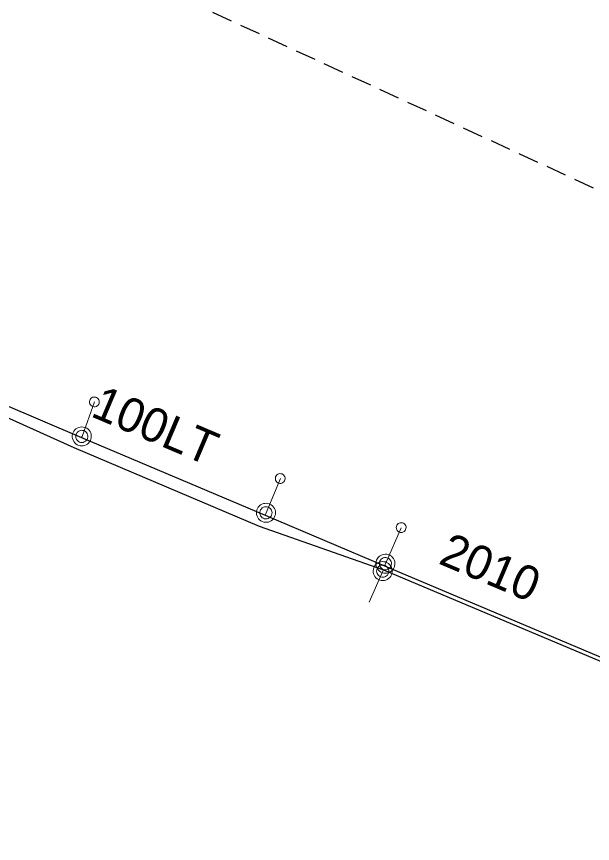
# Model space of a CAD drawing. Extents: x -735085 to -733500, y -1044153 to -1043402.
# Drawn here: x -734785.04 to -734758, y -1043558.45 to -1043519.6 of the extents above; entities that cross this region are included whole.
import ezdxf

# ---------------------------------------------------------------- set-up
doc = ezdxf.new("R2010")
doc.units = 0
doc.header["$LTSCALE"] = 0.32
doc.linetypes.add('MEDIUM_DASHED', pattern=[4.5, 3, -1.5])
doc.layers.add('15', color=7, linetype='Continuous')
doc.layers.add('63', color=7, linetype='MEDIUM_DASHED', lineweight=25)
doc.layers.add('8', color=7, linetype='Continuous', lineweight=13)

msp = doc.modelspace()

# ---------------------------------------------------------------- linework, layer by layer
at = {"layer": '63'}
msp.add_lwpolyline([(-734796.022, -1043808.279), (-734957.658, -1043641.023), (-734957.66, -1043641.021), (-735032.487, -1043496.398), (-735032.488, -1043496.396), (-735032.488, -1043496.394), (-735032.488, -1043496.393), (-735032.488, -1043496.391), (-735014.686, -1043433.916), (-735014.686, -1043433.914), (-735014.685, -1043433.913), (-735014.683, -1043433.911), (-735014.682, -1043433.91), (-735014.68, -1043433.909), (-735014.678, -1043433.909), (-735014.676, -1043433.909), (-734957.569, -1043435.5), (-734957.567, -1043435.5), (-734957.565, -1043435.501), (-734250.468, -1043761.931)], dxfattribs=at)
at = {"layer": '8'}
for p, q in [((-734767.84, -1043545.66), (-734768.48, -1043547.117)), ((-734767.807, -1043545.587), (-734767.84, -1043545.66))]:
    msp.add_line(p, q, dxfattribs=at)
at = {"layer": '8', "lineweight": 25}
for points in [[(-734798.6, -1043532.29), (-734781.989, -1043539.38), (-734773.37, -1043543.03), (-734767.76, -1043545.41), (-734738.719, -1043557.66), (-734737.059, -1043558.35)], [(-734792.71, -1043535.18), (-734782.352, -1043539.852), (-734773.644, -1043543.536), (-734767.807, -1043545.587), (-734738.734, -1043557.836), (-734732.528, -1043560.258), (-734709.46, -1043569.477), (-734674.151, -1043584.087)]]:
    msp.add_lwpolyline(points, dxfattribs=at)
at = {"layer": '8'}
for points in [[(-734781.315, -1043537.487), (-734781.366, -1043537.476), (-734781.419, -1043537.477), (-734781.47, -1043537.49), (-734781.517, -1043537.514), (-734781.557, -1043537.548), (-734781.588, -1043537.59), (-734781.609, -1043537.638), (-734781.619, -1043537.689), (-734781.617, -1043537.742), (-734781.603, -1043537.793), (-734781.577, -1043537.839), (-734781.542, -1043537.878), (-734781.499, -1043537.908), (-734781.451, -1043537.928), (-734781.399, -1043537.937), (-734781.347, -1043537.932), (-734781.296, -1043537.918), (-734781.25, -1043537.891), (-734781.213, -1043537.855), (-734781.183, -1043537.811), (-734781.165, -1043537.763), (-734781.158, -1043537.71), (-734781.163, -1043537.658), (-734781.18, -1043537.608), (-734781.207, -1043537.564), (-734781.244, -1043537.526), (-734781.289, -1043537.498)], [(-734781.835, -1043538.903), (-734781.907, -1043538.885), (-734781.98, -1043538.879), (-734782.052, -1043538.885), (-734782.123, -1043538.904), (-734782.191, -1043538.933), (-734782.252, -1043538.972), (-734782.305, -1043539.022), (-734782.351, -1043539.079), (-734782.386, -1043539.143), (-734782.411, -1043539.213), (-734782.424, -1043539.285), (-734782.424, -1043539.358), (-734782.413, -1043539.429), (-734782.391, -1043539.499), (-734782.357, -1043539.565), (-734782.313, -1043539.623), (-734782.259, -1043539.674), (-734782.199, -1043539.715), (-734782.133, -1043539.746), (-734782.062, -1043539.765), (-734781.99, -1043539.773), (-734781.917, -1043539.769), (-734781.845, -1043539.753), (-734781.778, -1043539.725), (-734781.715, -1043539.687), (-734781.66, -1043539.639), (-734781.613, -1043539.584), (-734781.575, -1043539.52), (-734781.549, -1043539.452), (-734781.534, -1043539.38), (-734781.532, -1043539.307), (-734781.541, -1043539.234), (-734781.562, -1043539.164), (-734781.593, -1043539.098), (-734781.636, -1043539.038), (-734781.687, -1043538.986), (-734781.747, -1043538.944), (-734781.812, -1043538.912)], [(-734781.887, -1043539.055), (-734781.944, -1043539.042), (-734782.003, -1043539.041), (-734782.06, -1043539.052), (-734782.114, -1043539.075), (-734782.163, -1043539.107), (-734782.204, -1043539.149), (-734782.235, -1043539.198), (-734782.256, -1043539.254), (-734782.265, -1043539.311), (-734782.261, -1043539.37), (-734782.247, -1043539.427), (-734782.221, -1043539.479), (-734782.185, -1043539.525), (-734782.14, -1043539.563), (-734782.089, -1043539.591), (-734782.032, -1043539.608), (-734781.974, -1043539.613), (-734781.916, -1043539.606), (-734781.861, -1043539.587), (-734781.81, -1043539.557), (-734781.767, -1043539.518), (-734781.732, -1043539.471), (-734781.707, -1043539.418), (-734781.695, -1043539.361), (-734781.693, -1043539.302), (-734781.704, -1043539.245), (-734781.727, -1043539.19), (-734781.759, -1043539.143), (-734781.801, -1043539.102), (-734781.851, -1043539.07)], [(-734772.573, -1043541.091), (-734772.624, -1043541.077), (-734772.677, -1043541.076), (-734772.728, -1043541.085), (-734772.777, -1043541.107), (-734772.818, -1043541.139), (-734772.851, -1043541.18), (-734772.875, -1043541.226), (-734772.888, -1043541.277), (-734772.888, -1043541.33), (-734772.877, -1043541.382), (-734772.853, -1043541.429), (-734772.821, -1043541.469), (-734772.779, -1043541.502), (-734772.732, -1043541.524), (-734772.68, -1043541.536), (-734772.628, -1043541.534), (-734772.577, -1043541.522), (-734772.53, -1043541.497), (-734772.491, -1043541.463), (-734772.459, -1043541.421), (-734772.438, -1043541.374), (-734772.428, -1043541.321), (-734772.431, -1043541.269), (-734772.445, -1043541.218), (-734772.47, -1043541.173), (-734772.505, -1043541.133), (-734772.548, -1043541.103)], [(-734773.165, -1043542.5), (-734773.235, -1043542.479), (-734773.308, -1043542.469), (-734773.381, -1043542.472), (-734773.452, -1043542.486), (-734773.521, -1043542.512), (-734773.584, -1043542.548), (-734773.64, -1043542.595), (-734773.689, -1043542.65), (-734773.727, -1043542.712), (-734773.755, -1043542.78), (-734773.772, -1043542.851), (-734773.776, -1043542.925), (-734773.769, -1043542.997), (-734773.75, -1043543.068), (-734773.719, -1043543.135), (-734773.678, -1043543.195), (-734773.628, -1043543.248), (-734773.57, -1043543.293), (-734773.505, -1043543.327), (-734773.436, -1043543.35), (-734773.364, -1043543.361), (-734773.29, -1043543.361), (-734773.218, -1043543.349), (-734773.149, -1043543.325), (-734773.085, -1043543.29), (-734773.027, -1043543.245), (-734772.977, -1043543.192), (-734772.937, -1043543.13), (-734772.907, -1043543.063), (-734772.889, -1043542.992), (-734772.882, -1043542.919), (-734772.888, -1043542.846), (-734772.905, -1043542.775), (-734772.933, -1043542.708), (-734772.973, -1043542.646), (-734773.021, -1043542.591), (-734773.079, -1043542.546), (-734773.142, -1043542.51)], [(-734773.224, -1043542.65), (-734773.28, -1043542.634), (-734773.339, -1043542.63), (-734773.397, -1043542.637), (-734773.452, -1043542.657), (-734773.502, -1043542.687), (-734773.545, -1043542.727), (-734773.579, -1043542.775), (-734773.603, -1043542.829), (-734773.614, -1043542.886), (-734773.614, -1043542.945), (-734773.602, -1043543.002), (-734773.579, -1043543.055), (-734773.545, -1043543.103), (-734773.502, -1043543.144), (-734773.453, -1043543.174), (-734773.397, -1043543.194), (-734773.339, -1043543.202), (-734773.281, -1043543.198), (-734773.225, -1043543.182), (-734773.172, -1043543.155), (-734773.128, -1043543.118), (-734773.09, -1043543.073), (-734773.063, -1043543.021), (-734773.048, -1043542.965), (-734773.043, -1043542.906), (-734773.051, -1043542.848), (-734773.071, -1043542.793), (-734773.101, -1043542.744), (-734773.141, -1043542.701), (-734773.189, -1043542.667)], [(-734766.753, -1043543.572), (-734766.767, -1043543.522), (-734766.793, -1043543.476), (-734766.828, -1043543.437), (-734766.871, -1043543.406), (-734766.92, -1043543.387), (-734766.972, -1043543.379), (-734767.024, -1043543.382), (-734767.074, -1043543.397), (-734767.119, -1043543.424), (-734767.158, -1043543.46), (-734767.186, -1043543.504), (-734767.205, -1043543.553), (-734767.212, -1043543.606), (-734767.206, -1043543.658), (-734767.19, -1043543.708), (-734767.162, -1043543.752), (-734767.125, -1043543.789), (-734767.08, -1043543.818), (-734767.031, -1043543.834), (-734766.979, -1043543.84), (-734766.927, -1043543.833), (-734766.877, -1043543.815), (-734766.833, -1043543.786), (-734766.797, -1043543.748), (-734766.771, -1043543.703), (-734766.754, -1043543.653), (-734766.751, -1043543.6)], [(-734767.519, -1043544.905), (-734767.587, -1043544.878), (-734767.659, -1043544.862), (-734767.731, -1043544.858), (-734767.804, -1043544.867), (-734767.875, -1043544.886), (-734767.941, -1043544.917), (-734768.001, -1043544.958), (-734768.054, -1043545.009), (-734768.098, -1043545.067), (-734768.132, -1043545.133), (-734768.154, -1043545.202), (-734768.165, -1043545.275), (-734768.164, -1043545.347), (-734768.151, -1043545.42), (-734768.126, -1043545.489), (-734768.091, -1043545.553), (-734768.045, -1043545.61), (-734767.991, -1043545.659), (-734767.93, -1043545.699), (-734767.862, -1043545.728), (-734767.792, -1043545.746), (-734767.719, -1043545.752), (-734767.646, -1043545.746), (-734767.575, -1043545.728), (-734767.508, -1043545.699), (-734767.447, -1043545.659), (-734767.392, -1043545.61), (-734767.346, -1043545.553), (-734767.311, -1043545.489), (-734767.286, -1043545.419), (-734767.274, -1043545.347), (-734767.273, -1043545.274), (-734767.284, -1043545.201), (-734767.306, -1043545.132), (-734767.341, -1043545.067), (-734767.384, -1043545.008), (-734767.437, -1043544.958), (-734767.497, -1043544.917)], [(-734767.724, -1043545.226), (-734767.796, -1043545.212), (-734767.869, -1043545.209), (-734767.942, -1043545.218), (-734768.011, -1043545.24), (-734768.078, -1043545.272), (-734768.137, -1043545.314), (-734768.188, -1043545.366), (-734768.232, -1043545.425), (-734768.264, -1043545.49), (-734768.286, -1043545.561), (-734768.295, -1043545.633), (-734768.292, -1043545.707), (-734768.279, -1043545.778), (-734768.253, -1043545.847), (-734768.216, -1043545.91), (-734768.17, -1043545.966), (-734768.114, -1043546.015), (-734768.052, -1043546.054), (-734767.984, -1043546.082), (-734767.913, -1043546.098), (-734767.841, -1043546.102), (-734767.768, -1043546.095), (-734767.697, -1043546.076), (-734767.631, -1043546.046), (-734767.57, -1043546.005), (-734767.517, -1043545.955), (-734767.472, -1043545.897), (-734767.437, -1043545.832), (-734767.414, -1043545.763), (-734767.403, -1043545.69), (-734767.403, -1043545.617), (-734767.416, -1043545.545), (-734767.439, -1043545.475), (-734767.474, -1043545.411), (-734767.519, -1043545.353), (-734767.573, -1043545.303), (-734767.634, -1043545.264), (-734767.7, -1043545.234)], [(-734767.591, -1043545.049), (-734767.646, -1043545.028), (-734767.704, -1043545.019), (-734767.762, -1043545.022), (-734767.819, -1043545.037), (-734767.871, -1043545.062), (-734767.917, -1043545.098), (-734767.955, -1043545.143), (-734767.984, -1043545.195), (-734768, -1043545.25), (-734768.005, -1043545.309), (-734767.998, -1043545.367), (-734767.98, -1043545.422), (-734767.951, -1043545.473), (-734767.911, -1043545.517), (-734767.865, -1043545.552), (-734767.811, -1043545.576), (-734767.754, -1043545.589), (-734767.695, -1043545.591), (-734767.638, -1043545.579), (-734767.583, -1043545.557), (-734767.536, -1043545.524), (-734767.494, -1043545.482), (-734767.463, -1043545.433), (-734767.443, -1043545.378), (-734767.433, -1043545.32), (-734767.436, -1043545.262), (-734767.451, -1043545.205), (-734767.477, -1043545.153), (-734767.513, -1043545.107), (-734767.557, -1043545.069)], [(-734767.769, -1043545.381), (-734767.826, -1043545.37), (-734767.885, -1043545.372), (-734767.942, -1043545.385), (-734767.995, -1043545.41), (-734768.042, -1043545.444), (-734768.081, -1043545.488), (-734768.111, -1043545.539), (-734768.129, -1043545.595), (-734768.135, -1043545.653), (-734768.129, -1043545.712), (-734768.112, -1043545.768), (-734768.084, -1043545.818), (-734768.046, -1043545.863), (-734767.999, -1043545.899), (-734767.947, -1043545.925), (-734767.89, -1043545.939), (-734767.832, -1043545.942), (-734767.774, -1043545.932), (-734767.719, -1043545.911), (-734767.67, -1043545.879), (-734767.629, -1043545.838), (-734767.596, -1043545.789), (-734767.574, -1043545.735), (-734767.564, -1043545.678), (-734767.564, -1043545.619), (-734767.578, -1043545.562), (-734767.603, -1043545.509), (-734767.638, -1043545.463), (-734767.682, -1043545.424), (-734767.732, -1043545.395)]]:
    msp.add_lwpolyline(points, close=True, dxfattribs=at)
for points in [[(-734781.989, -1043539.38), (-734781.969, -1043539.33), (-734781.379, -1043537.71)], [(-734773.37, -1043543.03), (-734773.32, -1043542.92), (-734772.649, -1043541.31)], [(-734767.76, -1043545.41), (-734767.71, -1043545.31), (-734766.98, -1043543.62)]]:
    msp.add_lwpolyline(points, dxfattribs=at)

# ---------------------------------------------------------------- texts
at = {"layer": '15'}
for s, p in [('100LT ', (-734781.618, -1043538.361)), ('2010', (-734765.284, -1043545.279))]:
    msp.add_text(s, height=1.6, rotation=337, dxfattribs=at).set_placement(p)

doc.saveas('drawing.dxf')
